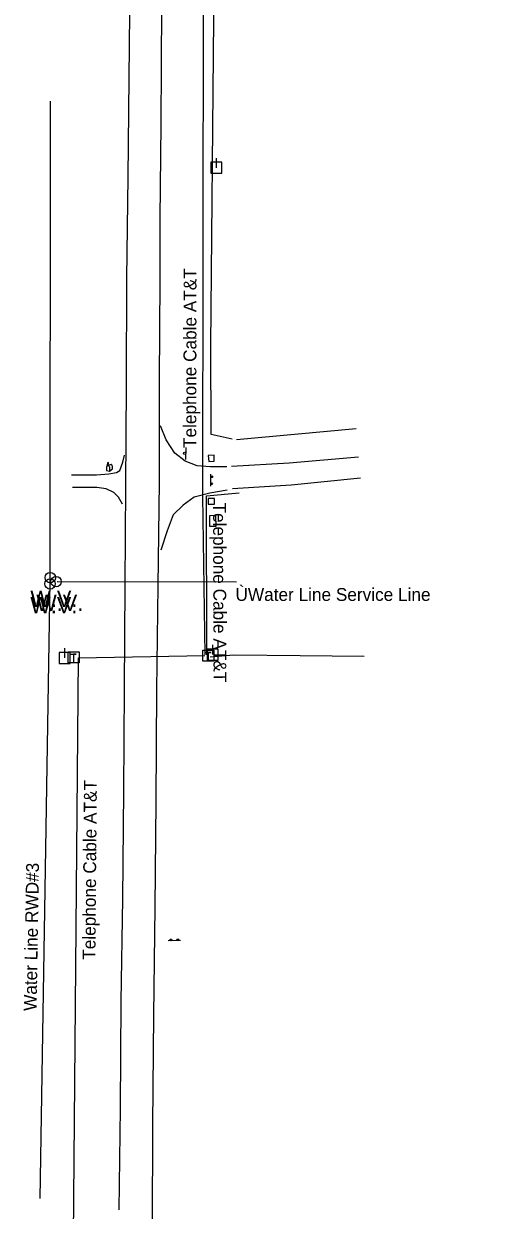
# Model space of a CAD drawing. Extents: x 19405533 to 19432306, y 137070 to 200991.
# Drawn here: x 19424047 to 19424391, y 152120 to 152983 of the extents above; entities that cross this region are included whole.
import ezdxf

# ---------------------------------------------------------------- set-up
doc = ezdxf.new("R2010")
doc.units = 0
for name, color, linetype in [('sv_Fence Existing_x_s', 7, 'Continuous'), ('sv_Mailbox_x_n', 7, 'Continuous'), ('sv_Pavement Edge_x_s', 7, 'Continuous'), ('sv_Poles Utility_x_n', 7, 'Continuous'), ('sv_Private Road_x_s', 7, 'Continuous'), ('sv_Retaining Wall_x_s', 7, 'Continuous'), ('sv_Signs Billboards_x_s', 7, 'Continuous'), ('sv_Telephone Line Label_x_n', 7, 'Continuous'), ('sv_Telephone Line_x_n', 7, 'Continuous'), ('sv_Water Line Label_x_n', 7, 'Continuous'), ('sv_Water Line_x_n', 7, 'Continuous')]:
    doc.layers.add(name, color=color, linetype=linetype)

msp = doc.modelspace()

# ---------------------------------------------------------------- linework, layer by layer
at = {"layer": 'sv_Fence Existing_x_s'}
msp.add_line((19424288.6, 152688.48), (19424201.83, 152680.43), dxfattribs=at)
for points in [[(19424198.66, 152680.78), (19424183.32, 152684.36), (19424183.07, 152748.85), (19424185.26, 152986.53), (19424188.44, 153182.99), (19424211.99, 153184.94), (19424212.99, 153213.73), (19424213.9, 153310.2), (19424216.03, 153384.23), (19424220.19, 153396.85), (19424222.91, 153414.79), (19424222.08, 153422.09), (19424217.6, 153446.82), (19424215.75, 153468.08), (19424212.32, 153487.77), (19424212.29, 153487.75), (19424215.06, 153545.21), (19424216.4, 153679.06), (19424230.48, 153702.8)], [(19424198.66, 152680.78), (19424183.32, 152684.36), (19424183.07, 152748.85), (19424185.26, 152986.53), (19424188.44, 153182.99), (19424211.99, 153184.94), (19424212.99, 153213.73), (19424213.9, 153310.2), (19424216.03, 153384.23), (19424220.19, 153396.85), (19424222.91, 153414.79), (19424222.08, 153422.09), (19424217.6, 153446.82), (19424215.75, 153468.08), (19424212.32, 153487.77), (19424212.29, 153487.75), (19424215.06, 153545.21), (19424216.4, 153679.06), (19424230.48, 153702.8)], [(19424198.66, 152680.78), (19424183.32, 152684.36), (19424183.07, 152748.85), (19424185.26, 152986.53), (19424188.44, 153182.99), (19424211.99, 153184.94), (19424212.99, 153213.73), (19424213.9, 153310.2), (19424216.03, 153384.23), (19424220.19, 153396.85), (19424222.91, 153414.79), (19424222.08, 153422.09), (19424217.6, 153446.82), (19424215.75, 153468.08), (19424212.32, 153487.77), (19424212.29, 153487.75), (19424215.06, 153545.21), (19424216.4, 153679.06), (19424230.48, 153702.8)], [(19424198.66, 152680.78), (19424183.32, 152684.36), (19424183.07, 152748.85), (19424185.26, 152986.53), (19424188.44, 153182.99), (19424211.99, 153184.94), (19424212.99, 153213.73), (19424213.9, 153310.2), (19424216.03, 153384.23), (19424220.19, 153396.85), (19424222.91, 153414.79), (19424222.08, 153422.09), (19424217.6, 153446.82), (19424215.75, 153468.08), (19424212.32, 153487.77), (19424212.29, 153487.75), (19424215.06, 153545.21), (19424216.4, 153679.06), (19424230.48, 153702.8)], [(19424182.7, 152522.56), (19424199.85, 152524.01), (19424248, 152523.48), (19424294.55, 152523.05)]]:
    msp.add_lwpolyline(points, dxfattribs=at)
at = {"layer": 'sv_Mailbox_x_n'}
msp.add_lwpolyline([(19424107.93, 152661.6), (19424108.04, 152661.68), (19424108.36, 152661.76), (19424108.78, 152661.61), (19424109.13, 152661.19), (19424109.36, 152660.55), (19424109.44, 152659.8), (19424109.44, 152657.69), (19424111.65, 152659.32), (19424111.65, 152660.51), (19424111.63, 152660.88), (19424111.47, 152661.58), (19424111.34, 152661.88), (19424111, 152662.31), (19424110.8, 152662.42), (19424110.57, 152662.47), (19424108.36, 152661.76), (19424108.04, 152661.68), (19424108.04, 152662.77), (19424108.76, 152662.94), (19424108.79, 152663.88), (19424107.98, 152663.68), (19424107.93, 152661.6), (19424107.6, 152661.19), (19424107.36, 152660.56), (19424107.28, 152659.81), (19424107.28, 152658.07), (19424109.44, 152657.69)], dxfattribs=at)
msp.add_lwpolyline([(19424107.93, 152661.6), (19424108.04, 152661.68), (19424108.36, 152661.76), (19424108.78, 152661.61), (19424109.13, 152661.19), (19424109.36, 152660.55), (19424109.44, 152659.8), (19424109.44, 152657.69), (19424111.65, 152659.32), (19424111.65, 152660.51), (19424111.63, 152660.88), (19424111.47, 152661.58), (19424111.34, 152661.88), (19424111, 152662.31), (19424110.8, 152662.42), (19424110.57, 152662.47), (19424108.36, 152661.76), (19424108.04, 152661.68), (19424108.04, 152662.77), (19424108.76, 152662.94), (19424108.79, 152663.88), (19424107.98, 152663.68), (19424107.93, 152661.6), (19424107.6, 152661.19), (19424107.36, 152660.56), (19424107.28, 152659.81), (19424107.28, 152658.07), (19424109.44, 152657.69)], dxfattribs=at)
at = {"layer": 'sv_Pavement Edge_x_s'}
for points in [[(19424157.44, 153876.62), (19424157.02, 153804.72), (19424157.99, 153793.9), (19424156.52, 153746.87), (19424155.04, 153736.59), (19424154.87, 153712.91), (19424154, 153641.72), (19424153.14, 153564.02), (19424152.29, 153486.3), (19424151.21, 153406.18), (19424150.2, 153326.78), (19424149.53, 153251.15), (19424148.68, 153159.75), (19424148.06, 153078.92), (19424147.34, 152995.78), (19424146.79, 152909.73), (19424146.14, 152841.54), (19424146.05, 152796.45)], [(19424122.05, 152797.8), (19424123.04, 152871.32), (19424123.84, 152943.27), (19424124.41, 153014.54), (19424124.9, 153084.27), (19424125.74, 153160.28), (19424126.52, 153237.67), (19424127.28, 153310.33), (19424128.03, 153379.58), (19424129.2, 153453.17), (19424130, 153548.43), (19424131, 153624.44), (19424131.89, 153703.43), (19424132.29, 153730.03), (19424130.29, 153742.44), (19424131.47, 153799.96), (19424132.26, 153821.31), (19424133.7, 153830.48), (19424134.09, 153863.52)], [(19424116.56, 152120.64), (19424117.48, 152194.36), (19424117.93, 152272.08), (19424119.08, 152346.73), (19424119.83, 152424.99), (19424120.25, 152499.58), (19424120.84, 152574.8), (19424121.43, 152646.51), (19424121.75, 152719.88), (19424122.05, 152797.8)], [(19424146.05, 152796.45), (19424145.55, 152723.39), (19424145.52, 152649.54), (19424144.48, 152574.24), (19424143.65, 152498.7), (19424143.05, 152417.55), (19424142.29, 152340.65), (19424141.49, 152262.16), (19424140.63, 152182.39), (19424140.4, 152107.51), (19424139.21, 152028.15), (19424138.08, 151953.31), (19424137.32, 151876.73), (19424137.12, 151806.4), (19424136.4, 151731.94), (19424135.11, 151664.57)], [(19424290.34, 152667.83), (19424240.04, 152663.35), (19424198.13, 152661.06)], [(19424198.84, 152645.1), (19424241.4, 152647.72), (19424291.96, 152652.62)]]:
    msp.add_lwpolyline(points, dxfattribs=at)
at = {"layer": 'sv_Poles Utility_x_n'}
for p, q in [((19424183.18, 152882.05), (19424183.27, 152882.14)), ((19424187.18, 152878.19), (19424187.18, 152885.22)), ((19424077, 152521.89), (19424077, 152528.92)), ((19424180.53, 152528.13), (19424180.62, 152528.22)), ((19424184.53, 152524.27), (19424184.53, 152531.3)), ((19424073, 152525.75), (19424073.09, 152525.84))]:
    msp.add_line(p, q, dxfattribs=at)
for points in [[(19424183.18, 152874.15), (19424191.18, 152874.15), (19424191.18, 152882.14), (19424183.18, 152882.14)], [(19424180.53, 152520.23), (19424188.53, 152520.23), (19424188.53, 152528.22), (19424180.53, 152528.22)], [(19424073, 152517.85), (19424080.99, 152517.85), (19424080.99, 152525.84), (19424073, 152525.84)]]:
    msp.add_lwpolyline(points, close=True, dxfattribs=at)
at = {"layer": 'sv_Private Road_x_s'}
for points in [[(19424194.61, 152660.85), (19424182.66, 152660.85), (19424173.23, 152661.36), (19424164.51, 152664.82), (19424156.83, 152670.71), (19424150.62, 152680.3), (19424146.56, 152690.55)], [(19424194.61, 152660.85), (19424182.66, 152660.85), (19424173.23, 152661.36), (19424164.51, 152664.82), (19424156.83, 152670.71), (19424150.62, 152680.3), (19424146.56, 152690.55)], [(19424194.61, 152660.85), (19424182.66, 152660.85), (19424173.23, 152661.36), (19424164.51, 152664.82), (19424156.83, 152670.71), (19424150.62, 152680.3), (19424146.56, 152690.55)], [(19424194.61, 152660.85), (19424182.66, 152660.85), (19424173.23, 152661.36), (19424164.51, 152664.82), (19424156.83, 152670.71), (19424150.62, 152680.3), (19424146.56, 152690.55)], [(19424081.83, 152654.81), (19424100.02, 152654.9), (19424109, 152655.59), (19424114.63, 152656.53), (19424116.88, 152658.17), (19424119.25, 152664.14), (19424120.29, 152669.18)], [(19424118.92, 152633.65), (19424115.94, 152638.69), (19424112.5, 152642.11), (19424107.15, 152644.79), (19424100.23, 152645.76), (19424092.31, 152645.71), (19424082.47, 152645.61)], [(19424194.93, 152643.68), (19424182.26, 152641.54), (19424170.88, 152638.68), (19424162.88, 152632.79), (19424155.84, 152625.92), (19424151.33, 152614.28), (19424146.74, 152600.22)], [(19424194.93, 152643.68), (19424182.26, 152641.54), (19424170.88, 152638.68), (19424162.88, 152632.79), (19424155.84, 152625.92), (19424151.33, 152614.28), (19424146.74, 152600.22)], [(19424194.93, 152643.68), (19424182.26, 152641.54), (19424170.88, 152638.68), (19424162.88, 152632.79), (19424155.84, 152625.92), (19424151.33, 152614.28), (19424146.74, 152600.22)], [(19424194.93, 152643.68), (19424182.26, 152641.54), (19424170.88, 152638.68), (19424162.88, 152632.79), (19424155.84, 152625.92), (19424151.33, 152614.28), (19424146.74, 152600.22)]]:
    msp.add_lwpolyline(points, dxfattribs=at)
at = {"layer": 'sv_Retaining Wall_x_s'}
for points in [[(19424181.57, 152664.59), (19424185.63, 152664.87), (19424185.6, 152669.31), (19424181.28, 152669), (19424181.57, 152664.59)], [(19424181.57, 152664.59), (19424185.63, 152664.87), (19424185.6, 152669.31), (19424181.28, 152669), (19424181.57, 152664.59)], [(19424181.57, 152664.59), (19424185.63, 152664.87), (19424185.6, 152669.31), (19424181.28, 152669), (19424181.57, 152664.59)], [(19424181.57, 152664.59), (19424185.63, 152664.87), (19424185.6, 152669.31), (19424181.28, 152669), (19424181.57, 152664.59)], [(19424185.72, 152633.7), (19424185.65, 152637.61), (19424181.11, 152637.6), (19424181.2, 152633.53), (19424185.72, 152633.7)], [(19424185.72, 152633.7), (19424185.65, 152637.61), (19424181.11, 152637.6), (19424181.2, 152633.53), (19424185.72, 152633.7)], [(19424185.72, 152633.7), (19424185.65, 152637.61), (19424181.11, 152637.6), (19424181.2, 152633.53), (19424185.72, 152633.7)], [(19424185.72, 152633.7), (19424185.65, 152637.61), (19424181.11, 152637.6), (19424181.2, 152633.53), (19424185.72, 152633.7)], [(19424182.29, 152617.41), (19424182.3, 152625.4), (19424186.54, 152625.67), (19424186.72, 152617.41), (19424182.29, 152617.41)], [(19424182.29, 152617.41), (19424182.3, 152625.4), (19424186.54, 152625.67), (19424186.72, 152617.41), (19424182.29, 152617.41)], [(19424182.29, 152617.41), (19424182.3, 152625.4), (19424186.54, 152625.67), (19424186.72, 152617.41), (19424182.29, 152617.41)], [(19424182.29, 152617.41), (19424182.3, 152625.4), (19424186.54, 152625.67), (19424186.72, 152617.41), (19424182.29, 152617.41)]]:
    msp.add_lwpolyline(points, dxfattribs=at)
at = {"layer": 'sv_Signs Billboards_x_s'}
for p, q in [((19424165.01, 152666.05), (19424165.06, 152674.9)), ((19424183.09, 152646.56), (19424183.18, 152655.41)), ((19424161.05, 152316.34), (19424152.2, 152316.17))]:
    msp.add_line(p, q, dxfattribs=at)
for centre, radius in [((19424164.15, 152670.48), 0.885), ((19424183.74, 152648.45), 0.632), ((19424183.79, 152653.51), 0.632), ((19424154.09, 152316.84), 0.632), ((19424159.14, 152316.94), 0.632)]:
    msp.add_circle(centre, radius, dxfattribs=at)
at = {"layer": 'sv_Telephone Line_x_n'}
for points in [[(19424178.93, 152524.12), (19424177.23, 152639.3), (19424178.98, 153815.12), (19424208.2, 153815.72), (19424181.79, 153823.16), (19424195.84, 154938.92), (19424203.91, 154944.62), (19424194.73, 154948.5), (19424203.7, 155703.93), (19424211.33, 155710.27), (19424203.2, 155713.2), (19424208.16, 156250.28), (19424216.09, 156255.01), (19424209.42, 156263.34), (19424211.47, 156932.7), (19424190.27, 156958.51), (19424190.81, 156972.31), (19424219.09, 157002.35), (19424235.46, 158756.35), (19424249.09, 160231.17), (19424255.54, 160239.34), (19424256.24, 160263.97), (19424248.99, 160267.38), (19424266.14, 161627.21)], [(19424180.22, 152524.14), (19424179.91, 152639.58), (19424203.72, 152641.95)], [(19424081.27, 152524.48), (19424085.35, 152524.48), (19424083.34, 152524.48), (19424083.34, 152518.23), (19424079.34, 152518.23), (19424079.34, 152526.23), (19424087.33, 152526.23), (19424087.33, 152518.23), (19424083.34, 152518.23)], [(19424179.15, 152525.79), (19424183.23, 152525.79), (19424181.21, 152525.79), (19424181.21, 152519.55), (19424177.22, 152519.55), (19424177.22, 152527.54), (19424185.21, 152527.54), (19424185.21, 152519.55), (19424181.21, 152519.55)], [(19427229.16, 142027.88), (19427228.39, 142031.63), (19427198.45, 142104.29), (19427188.61, 142121.55), (19426160.17, 144588.99), (19425460.11, 146288.41), (19424575.28, 148391.71), (19424375.41, 148922.76), (19424207.25, 149536.36), (19424142.15, 149948.4), (19424076.56, 150563.37), (19424075.67, 150590.13), (19424077.6, 151386.86), (19424086.85, 152521.9), (19424178.69, 152523.65)]]:
    msp.add_lwpolyline(points, dxfattribs=at)
at = {"layer": 'sv_Water Line_x_n'}
msp.add_line((19424071.37, 152577.41), (19424201.8, 152577.03), dxfattribs=at)
msp.add_lwpolyline([(19424059.04, 152128.84), (19424066.46, 152577.94), (19424066.56, 152926.48)], dxfattribs=at)
for centre in [(19424066.31, 152575.59), (19424066.38, 152580.17), (19424070.65, 152577.26)]:
    msp.add_circle(centre, 3.78, dxfattribs=at)

# ---------------------------------------------------------------- texts
at = {"layer": 'sv_Telephone Line Label_x_n'}
for rotation, p in [(89.91487, (19424172.49, 152674.43)), (270.15337, (19424184.72, 152634.74)), (89.53278, (19424099.21, 152302.36))]:
    msp.add_text('Telephone Cable AT&T', height=9.35, rotation=rotation, dxfattribs=at).set_placement(p)
at = {"layer": 'sv_Water Line Label_x_n'}
msp.add_text('ÙWater Line Service Line', height=9.35, dxfattribs=at).set_placement((19424201, 152563.25))
msp.add_text('Water Line RWD#3', height=9.35, rotation=89.05396, dxfattribs=at).set_placement((19424056.49, 152265.13))
at = {"layer": 'sv_Water Line_x_n'}
for p in [(19424051.97, 152558.93), (19424051.91, 152554.35), (19424056.25, 152556.02)]:
    msp.add_text('W.V.', height=11.8, dxfattribs=at).set_placement(p)

doc.saveas('drawing.dxf')
